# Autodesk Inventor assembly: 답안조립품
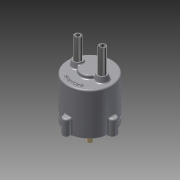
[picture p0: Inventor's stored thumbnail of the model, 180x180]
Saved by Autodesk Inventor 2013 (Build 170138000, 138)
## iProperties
Created: 2015-02
Part Number: 답안조립품
Document SubType Name: Assembly
Designer: WINDOWS7
Mass: 1967.32 g
Surface Area: 1692.75 cm^2
Volume: 412.891 cm^3
Density: 4.76475 g/cm^3
Author: WINDOWS7
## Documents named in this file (13)
- C:\Users\WINDOWS7\Desktop\350208V1018\답안조립품.iam
- C:\Users\WINDOWS7\Desktop\350208V1018\몸체.ipt
- C:\Users\WINDOWS7\Desktop\350208V1018\커버.ipt
- C:\Users\WINDOWS7\Desktop\350208V1018\M5x0.5x20.ipt
- C:\Users\WINDOWS7\Desktop\350208V1018\오일실.ipt
- C:\Users\WINDOWS7\Desktop\350208V1018\베어링 NA 4900.ipt
- C:\Users\WINDOWS7\Desktop\350208V1018\메인 축.ipt
- C:\Users\WINDOWS7\Desktop\350208V1018\멈춤링 22 x 1.2.ipt
- C:\Users\WINDOWS7\Desktop\350208V1018\멈춤링 10 x 1.ipt
- C:\Users\WINDOWS7\Desktop\350208V1018\판캠.ipt
- C:\Users\WINDOWS7\Desktop\350208V1018\슬라이드 축.ipt
- C:\Users\WINDOWS7\Desktop\350208V1018\가변스프링1.ipt
- C:\Users\WINDOWS7\Desktop\350208V1018\가변스프링2.ipt
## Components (6 placed, 3 different names)
1. 가변스프링1:1
2. 가변스프링2:1
3. M5x0.5x20:1
4. M5x0.5x20:2
5. M5x0.5x20:3
6. M5x0.5x20:4
